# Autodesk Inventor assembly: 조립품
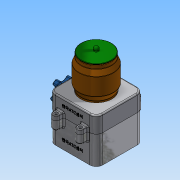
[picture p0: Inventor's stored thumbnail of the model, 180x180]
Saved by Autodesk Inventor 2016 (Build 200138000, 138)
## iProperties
Created: 2018-01
Part Number: 조립품
Material: 일반
Document SubType Name: Assembly
Designer: Administrator
Author: Administrator
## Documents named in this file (8)
- C:\Users\Administrator\Desktop\480107V1027\조립품.iam
- C:\Users\Administrator\Desktop\480107V1027\본체.ipt
- C:\Users\Administrator\Desktop\480107V1027\용기.ipt
- C:\Users\Administrator\Desktop\480107V1027\본체커버.ipt
- C:\Users\Administrator\Desktop\480107V1027\핸들축.ipt
- C:\Users\Administrator\Desktop\480107V1027\핸들.ipt
- C:\Users\Administrator\Desktop\480107V1027\볼트 M3x12.ipt
- C:\Users\Administrator\Desktop\480107V1027\용기캡.ipt
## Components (2 placed, 2 different names)
1. 핸들축:1
2. 핸들:1
